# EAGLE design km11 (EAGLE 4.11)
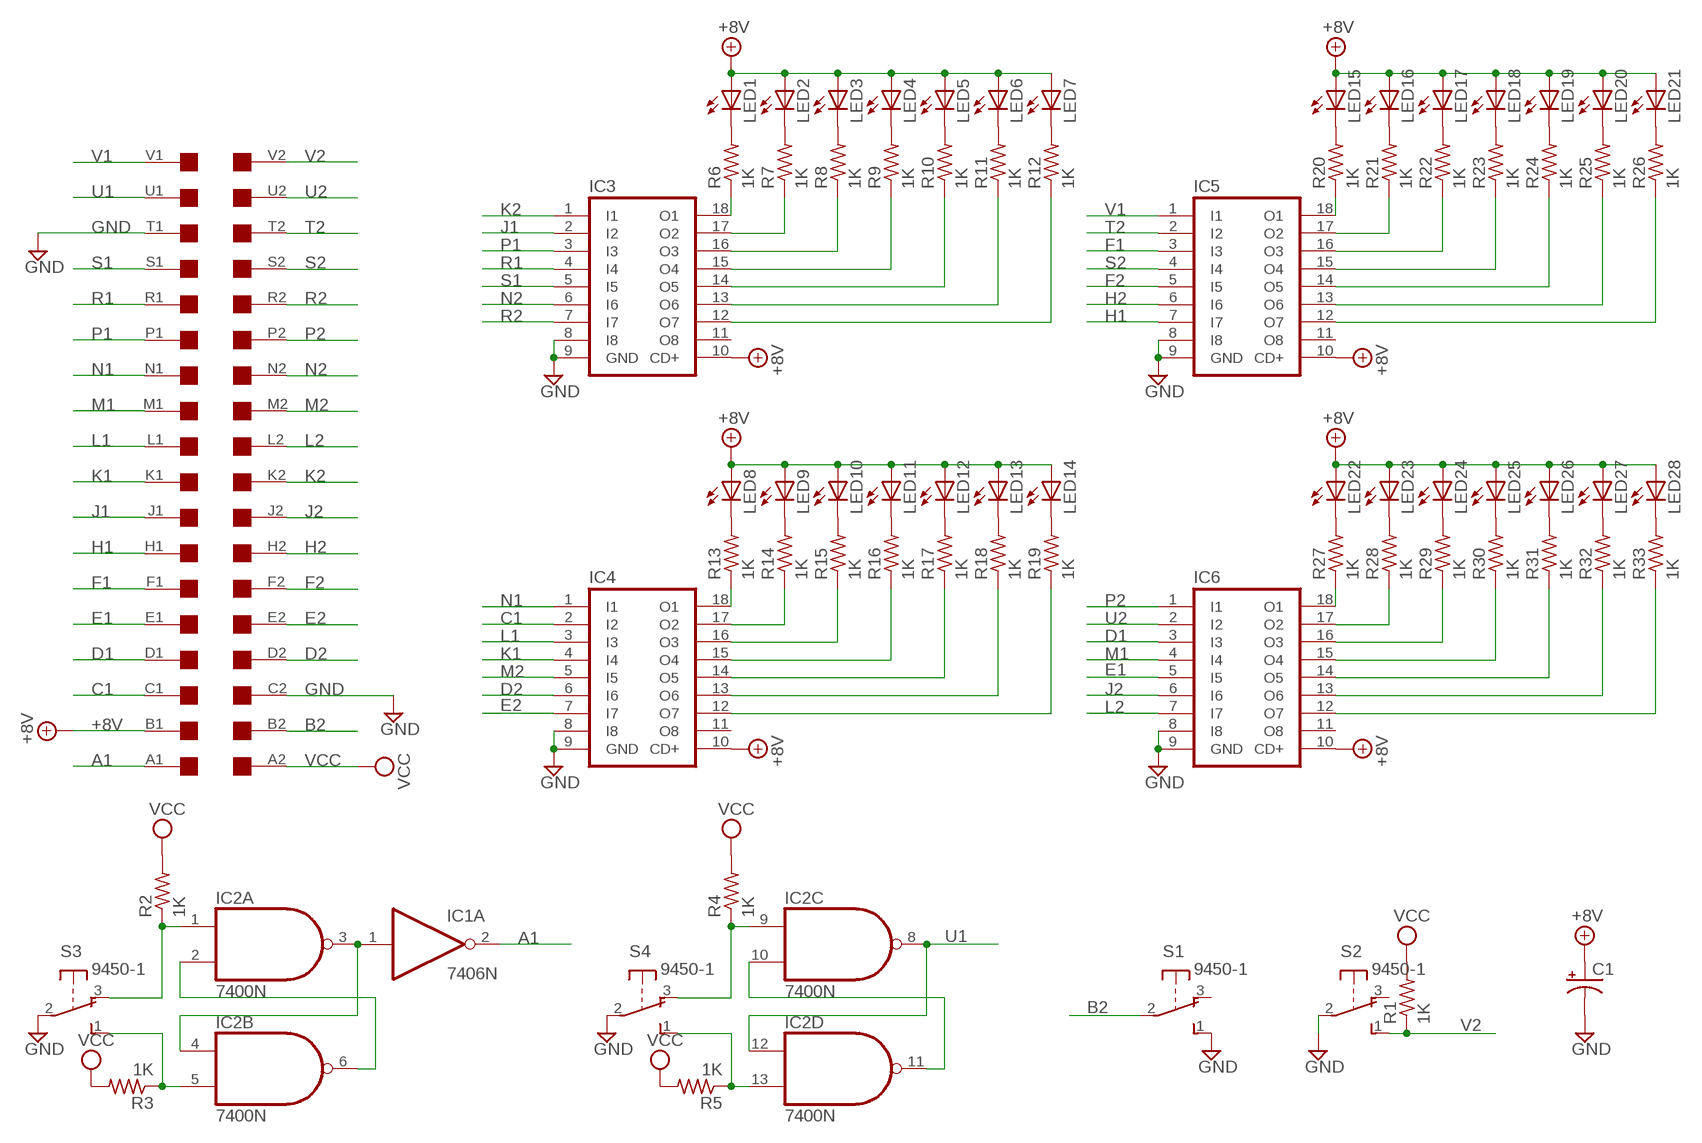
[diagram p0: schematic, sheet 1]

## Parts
C1  CPOL-USE22-6AXIAL  [E22-6]
IC1  7406N  [DIL14]
IC2  7400N  [DIL14]
IC3  ULN2803A  [DIL18]
IC4  ULN2803A  [DIL18]
IC5  ULN2803A  [DIL18]
IC6  ULN2803A  [DIL18]
LED1  LED3MM  [LED3MM]
LED2  LED3MM  [LED3MM]
LED3  LED3MM  [LED3MM]
LED4  LED3MM  [LED3MM]
LED5  LED3MM  [LED3MM]
LED6  LED3MM  [LED3MM]
LED7  LED3MM  [LED3MM]
LED8  LED3MM  [LED3MM]
LED9  LED3MM  [LED3MM]
LED10  LED3MM  [LED3MM]
LED11  LED3MM  [LED3MM]
LED12  LED3MM  [LED3MM]
LED13  LED3MM  [LED3MM]
LED14  LED3MM  [LED3MM]
LED15  LED3MM  [LED3MM]
LED16  LED3MM  [LED3MM]
LED17  LED3MM  [LED3MM]
LED18  LED3MM  [LED3MM]
LED19  LED3MM  [LED3MM]
LED20  LED3MM  [LED3MM]
LED21  LED3MM  [LED3MM]
LED22  LED3MM  [LED3MM]
LED23  LED3MM  [LED3MM]
LED24  LED3MM  [LED3MM]
LED25  LED3MM  [LED3MM]
LED26  LED3MM  [LED3MM]
LED27  LED3MM  [LED3MM]
LED28  LED3MM  [LED3MM]
R1  1K  R-US_0207/10  [0207/10]
R2  1K  R-US_0207/10  [0207/10]
R3  1K  R-US_0207/10  [0207/10]
R4  1K  R-US_0207/10  [0207/10]
R5  1K  R-US_0207/10  [0207/10]
R6  1K  R-US_0207/10  [0207/10]
R7  1K  R-US_0207/10  [0207/10]
R8  1K  R-US_0207/10  [0207/10]
R9  1K  R-US_0207/10  [0207/10]
R10  1K  R-US_0207/10  [0207/10]
R11  1K  R-US_0207/10  [0207/10]
R12  1K  R-US_0207/10  [0207/10]
R13  1K  R-US_0207/10  [0207/10]
R14  1K  R-US_0207/10  [0207/10]
R15  1K  R-US_0207/10  [0207/10]
R16  1K  R-US_0207/10  [0207/10]
R17  1K  R-US_0207/10  [0207/10]
R18  1K  R-US_0207/10  [0207/10]
R19  1K  R-US_0207/10  [0207/10]
R20  1K  R-US_0207/10  [0207/10]
R21  1K  R-US_0207/10  [0207/10]
R22  1K  R-US_0207/10  [0207/10]
R23  1K  R-US_0207/10  [0207/10]
R24  1K  R-US_0207/10  [0207/10]
R25  1K  R-US_0207/10  [0207/10]
R26  1K  R-US_0207/10  [0207/10]
R27  1K  R-US_0207/10  [0207/10]
R28  1K  R-US_0207/10  [0207/10]
R29  1K  R-US_0207/10  [0207/10]
R30  1K  R-US_0207/10  [0207/10]
R31  1K  R-US_0207/10  [0207/10]
R32  1K  R-US_0207/10  [0207/10]
R33  1K  R-US_0207/10  [0207/10]
S1  9450-1  [9450-1]
S2  9450-1  [9450-1]
S3  9450-1  [9450-1]
S4  9450-1  [9450-1]
U$1  EDGE-2  [EDGE-CON2]

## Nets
+8V: C1.+ IC3.10(CD+) IC4.10(CD+) IC5.10(CD+) IC6.10(CD+) LED1.A LED2.A LED3.A LED4.A LED5.A LED6.A LED7.A LED8.A LED9.A LED10.A LED11.A LED12.A LED13.A LED14.A LED15.A LED16.A LED17.A LED18.A LED19.A LED20.A LED21.A LED22.A LED23.A LED24.A LED25.A LED26.A LED27.A LED28.A U$1.B1
A1: IC1.2(A:O) U$1.A1
B2: S1.2(P) U$1.B2
C1: IC4.2(I2) U$1.C1
D1: IC6.3(I3) U$1.D1
D2: IC4.6(I6) U$1.D2
E1: IC6.5(I5) U$1.E1
E2: IC4.7(I7) U$1.E2
F1: IC5.3(I3) U$1.F1
F2: IC5.5(I5) U$1.F2
GND: C1.- IC3.8(I8) IC3.9(GND) IC4.8(I8) IC4.9(GND) IC5.8(I8) IC5.9(GND) IC6.8(I8) IC6.9(GND) S1.1(S) S2.2(P) S3.2(P) S4.2(P) U$1.C2 U$1.T1
H1: IC5.7(I7) U$1.H1
H2: IC5.6(I6) U$1.H2
J1: IC3.2(I2) U$1.J1
J2: IC6.6(I6) U$1.J2
K1: IC4.4(I4) U$1.K1
K2: IC3.1(I1) U$1.K2
L1: IC4.3(I3) U$1.L1
L2: IC6.7(I7) U$1.L2
M1: IC6.4(I4) U$1.M1
M2: IC4.5(I5) U$1.M2
N1: IC4.1(I1) U$1.N1
N2: IC3.6(I6) U$1.N2
N$1: IC1.1(A:I) IC2.3(A:O) IC2.4(B:I0)
N$2: IC2.2(A:I1) IC2.6(B:O)
N$3: IC2.5(B:I1) R3.1 S3.1(S)
N$4: IC2.1(A:I0) R2.1 S3.3(O)
N$5: LED1.K(C) R6.2
N$6: IC2.10(C:I1) IC2.11(D:O)
N$7: IC2.13(D:I1) R5.1 S4.1(S)
N$8: IC2.9(C:I0) R4.1 S4.3(O)
N$9: IC3.18(O1) R6.1
N$10: LED2.K(C) R7.2
N$11: LED3.K(C) R8.2
N$12: LED4.K(C) R9.2
N$13: LED5.K(C) R10.2
N$14: LED6.K(C) R11.2
N$15: LED7.K(C) R12.2
N$16: IC3.17(O2) R7.1
N$17: IC3.16(O3) R8.1
N$18: IC3.15(O4) R9.1
N$19: IC3.14(O5) R10.1
N$20: IC3.13(O6) R11.1
N$21: IC3.12(O7) R12.1
N$29: LED8.K(C) R13.2
N$30: IC4.18(O1) R13.1
N$31: LED9.K(C) R14.2
N$32: LED10.K(C) R15.2
N$33: LED11.K(C) R16.2
N$34: LED12.K(C) R17.2
N$35: LED13.K(C) R18.2
N$36: LED14.K(C) R19.2
N$37: IC4.17(O2) R14.1
N$38: IC4.16(O3) R15.1
N$39: IC4.15(O4) R16.1
N$40: IC4.14(O5) R17.1
N$41: IC4.13(O6) R18.1
N$42: IC4.12(O7) R19.1
N$43: LED15.K(C) R20.2
N$44: IC5.18(O1) R20.1
N$45: LED16.K(C) R21.2
N$46: LED17.K(C) R22.2
N$47: LED18.K(C) R23.2
N$48: LED19.K(C) R24.2
N$49: LED20.K(C) R25.2
N$50: LED21.K(C) R26.2
N$51: IC5.17(O2) R21.1
N$52: IC5.16(O3) R22.1
N$53: IC5.15(O4) R23.1
N$54: IC5.14(O5) R24.1
N$55: IC5.13(O6) R25.1
N$56: IC5.12(O7) R26.1
N$57: LED22.K(C) R27.2
N$58: IC6.18(O1) R27.1
N$59: LED23.K(C) R28.2
N$60: LED24.K(C) R29.2
N$61: LED25.K(C) R30.2
N$62: LED26.K(C) R31.2
N$63: LED27.K(C) R32.2
N$64: LED28.K(C) R33.2
N$65: IC6.17(O2) R28.1
N$66: IC6.16(O3) R29.1
N$67: IC6.15(O4) R30.1
N$68: IC6.14(O5) R31.1
N$69: IC6.13(O6) R32.1
N$70: IC6.12(O7) R33.1
P1: IC3.3(I3) U$1.P1
P2: IC6.1(I1) U$1.P2
R1: IC3.4(I4) U$1.R1
R2: IC3.7(I7) U$1.R2
S1: IC3.5(I5) U$1.S1
S2: IC5.4(I4) U$1.S2
T2: IC5.2(I2) U$1.T2
U1: IC2.8(C:O) IC2.12(D:I0) U$1.U1
U2: IC6.2(I2) U$1.U2
V1: IC5.1(I1) U$1.V1
V2: R1.1 S2.1(S) U$1.V2
VCC: R1.2 R2.2 R3.2 R4.2 R5.2 U$1.A2
Unconnected: IC1.3(B:I) IC1.4(B:O) IC1.5(C:I) IC1.6(C:O) IC1.8(D:O) IC1.9(D:I) IC1.10(E:O) IC1.11(E:I) IC1.12(F:O) IC1.13(F:I) IC3.11(O8) IC4.11(O8) IC5.11(O8) IC6.11(O8) S1.3(O) S2.3(O)

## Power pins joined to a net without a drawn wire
GND: IC1.7(P:GND) IC2.7(P:GND)
VCC: IC1.14(P:VCC) IC2.14(P:VCC)

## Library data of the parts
C1 = rcl:CPOL-US: POLARIZED CAPACITOR, American symbol
IC1 = 74xx-us:74*06: Hex INVERTER, open collector high-voltage output
IC2 = 74xx-us:74*00: Quad 2-input NAND gate
IC3-IC6 = uln-udn:ULN2803A: DRIVER ARRAY
LED1-LED28 = led:LED: LED
R1-R33 = rcl:R-US_: RESISTOR, American symbol
S1-S4 = switch-misc:9450-1: MARQUARDT SWITCH
U$1 = dec-con:EDGE-2: Double-Sided DEC edge connector.

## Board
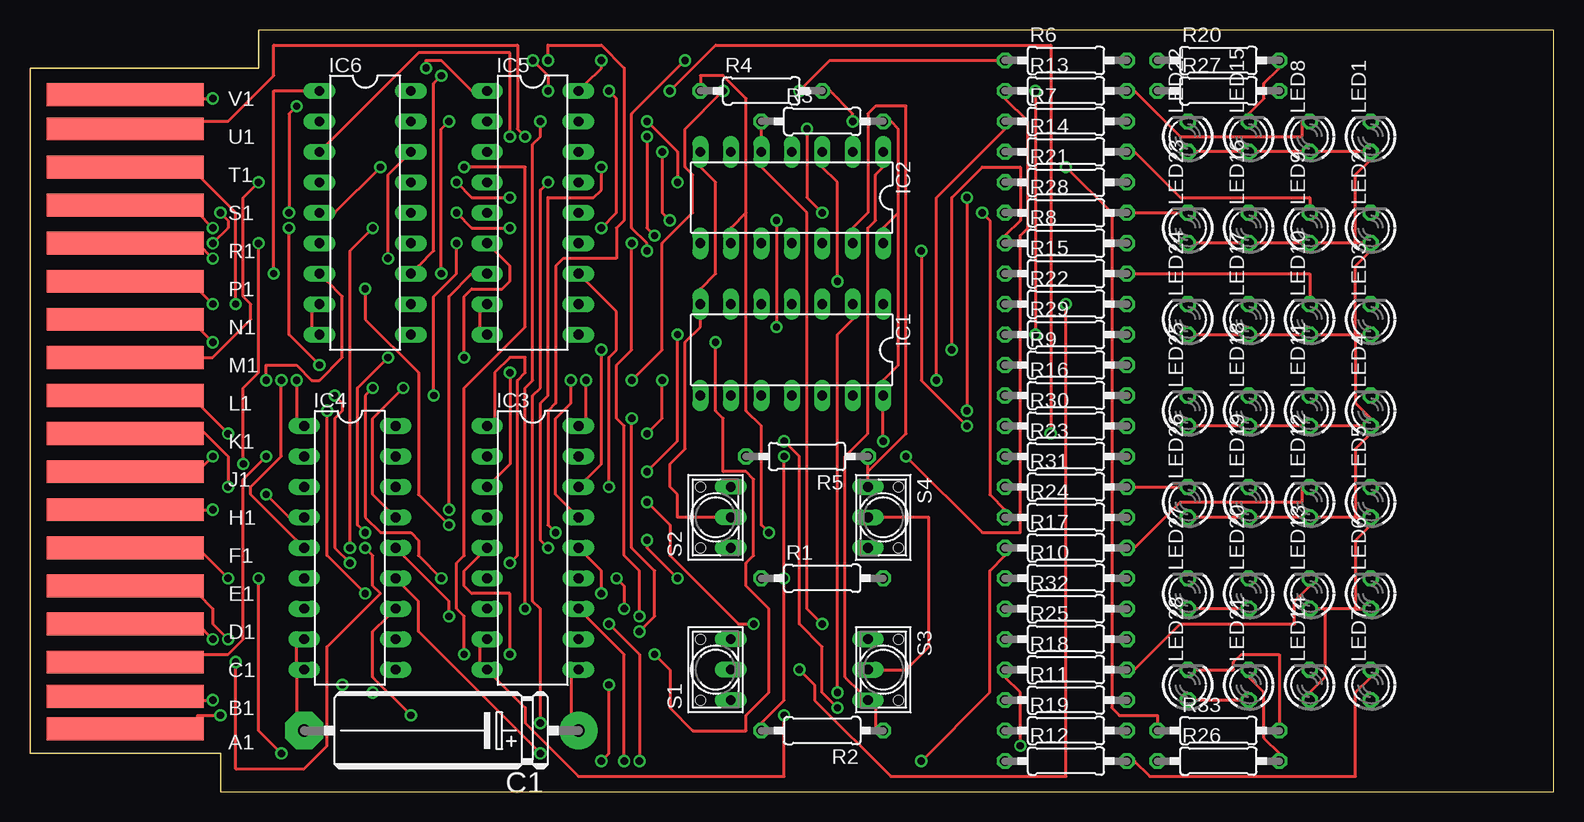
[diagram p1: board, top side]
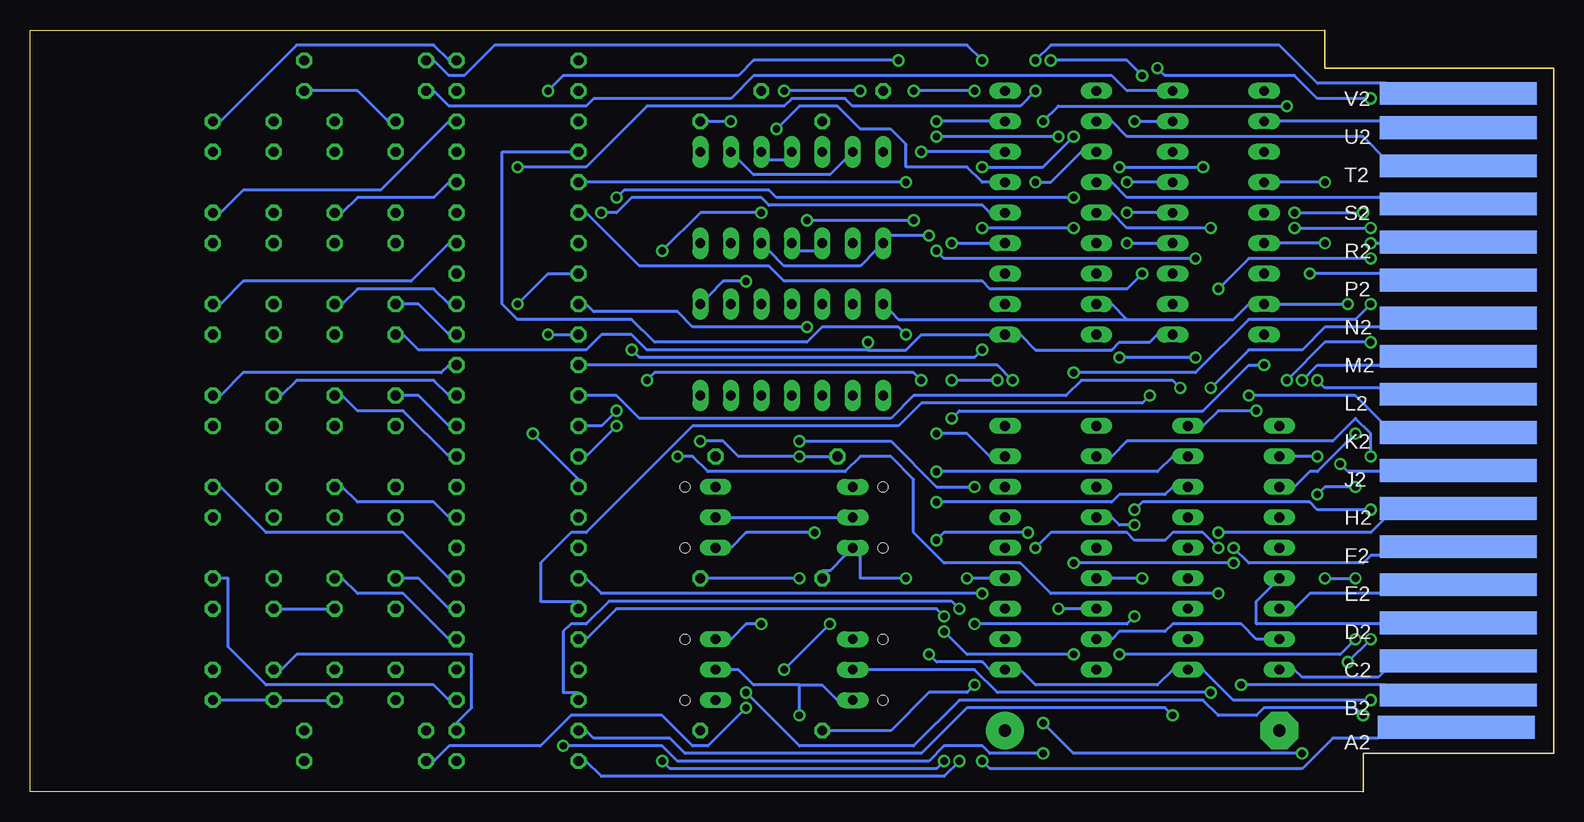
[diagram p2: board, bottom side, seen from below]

Size 127 x 63.5 mm. Coordinates in mm from the lower left corner, seen from the top.
Outline: 15.88,0 127,0 127,63.5 19.05,63.5
Copper layers (1*16): Top 0.035mm / dielectric 1.5mm / Bottom 0.035mm
Design rules "default": minimum track width 10mil, minimum drill 24mil, track to track 8mil, track to pad 8mil, pad to pad 8mil, via to via 8mil, smd to smd 8mil, copper to edge 40mil, drill to drill 8mil, minimum pad ring 10mil, minimum via ring 8mil, stop-mask expansion 4mil, vias tented up to drill 0mil, thermal gap 10mil

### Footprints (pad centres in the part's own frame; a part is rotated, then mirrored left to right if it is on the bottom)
E22-6 = drill 1.016 pad 3.15 round: + -11.43,0 | drill 1.016 pad 3.15 octagon: - 11.43,0
DIL14 = drill 0.813 long: 1 -7.62,-3.81; 2 -5.08,-3.81; 3 -2.54,-3.81; 4 0,-3.81; 5 2.54,-3.81; 6 5.08,-3.81; 7 7.62,-3.81; 8 7.62,3.81; 9 5.08,3.81; 10 2.54,3.81; 11 0,3.81; 12 -2.54,3.81; 13 -5.08,3.81; 14 -7.62,3.81
DIL18 = drill 0.813 long: 1 -10.16,-3.81; 2 -7.62,-3.81; 3 -5.08,-3.81; 4 -2.54,-3.81; 5 0,-3.81; 6 2.54,-3.81; 7 5.08,-3.81; 8 7.62,-3.81; 9 10.16,-3.81; 10 10.16,3.81; 11 7.62,3.81; 12 5.08,3.81; 13 2.54,3.81; 14 0,3.81; 15 -2.54,3.81; 16 -5.08,3.81; 17 -7.62,3.81; 18 -10.16,3.81
LED3MM = drill 0.813 octagon: A -1.27,0; K 1.27,0
0207/10 = drill 0.813 octagon: 1 -5.08,0; 2 5.08,0
9450-1 = drill 0.813 long: 1 -2.54,-1.27; 2 0,-1.27; 3 2.54,-1.27 | hole 0.813: 2.54,1.27; -2.54,1.27
EDGE-CON2 = smd 13.106 x 1.905: A1 7.938,5.239; B1 7.938,7.938; C1 7.938,10.795; D1 7.938,13.97; E1 7.938,17.145; F1 7.938,20.32; H1 7.938,23.495; J1 7.938,26.67; K1 7.938,29.845; L1 7.938,33.02; M1 7.938,36.195; N1 7.938,39.37; P1 7.938,42.545; R1 7.938,45.72; S1 7.938,48.895; T1 7.938,52.07; U1 7.938,55.245; V1 7.938,58.102 | smd 13.106 x 1.905 bottom: A2 8.096,5.34; B2 7.938,8.039; C2 7.938,10.897; D2 7.938,14.072; E2 7.938,17.247; F2 7.938,20.422; H2 7.938,23.597; J2 7.938,26.772; K2 7.938,29.947; L2 7.938,33.122; M2 7.938,36.297; N2 7.938,39.472; P2 7.938,42.647; R2 7.938,45.822; S2 7.938,48.997; T2 7.938,52.172; U2 7.938,55.347; V2 7.938,58.204

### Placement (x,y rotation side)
C1  34.29,5.08 180 top
IC1  63.5,36.83 180 top
IC2  63.5,49.53 180 top
IC3  41.91,20.32 270 top
IC4  26.67,20.32 270 top
IC5  41.91,48.26 270 top
IC6  27.94,48.26 270 top
LED1  111.76,54.61 90 top
LED2  111.76,46.99 90 top
LED3  111.76,39.37 90 top
LED4  111.76,31.75 90 top
LED5  111.76,24.13 90 top
LED6  111.76,16.51 90 top
LED7  111.76,8.89 90 top
LED8  106.68,54.61 90 top
LED9  106.68,46.99 90 top
LED10  106.68,39.37 90 top
LED11  106.68,31.75 90 top
LED12  106.68,24.13 90 top
LED13  106.68,16.51 90 top
LED14  106.68,8.89 90 top
LED15  101.6,54.61 90 top
LED16  101.6,46.99 90 top
LED17  101.6,39.37 90 top
LED18  101.6,31.75 90 top
LED19  101.6,24.13 90 top
LED20  101.6,16.51 90 top
LED21  101.6,8.89 90 top
LED22  96.52,54.61 90 top
LED23  96.52,46.99 90 top
LED24  96.52,39.37 90 top
LED25  96.52,31.75 90 top
LED26  96.52,24.13 90 top
LED27  96.52,16.51 90 top
LED28  96.52,8.89 90 top
R1  66.04,17.78 0 top
R2  66.04,5.08 180 top
R3  66.04,55.88 0 top
R4  60.96,58.42 0 top
R5  64.77,27.94 180 top
R6  86.36,60.96 0 top
R7  86.36,55.88 0 top
R8  86.36,45.72 0 top
R9  86.36,35.56 0 top
R10  86.36,17.78 0 top
R11  86.36,7.62 0 top
R12  86.36,2.54 0 top
R13  86.36,58.42 0 top
R14  86.36,53.34 0 top
R15  86.36,43.18 0 top
R16  86.36,33.02 0 top
R17  86.36,20.32 0 top
R18  86.36,10.16 0 top
R19  86.36,5.08 0 top
R20  99.06,60.96 0 top
R21  86.36,50.8 0 top
R22  86.36,40.64 0 top
R23  86.36,27.94 0 top
R24  86.36,22.86 0 top
R25  86.36,12.7 0 top
R26  99.06,2.54 0 top
R27  99.06,58.42 0 top
R28  86.36,48.26 0 top
R29  86.36,38.1 0 top
R30  86.36,30.48 0 top
R31  86.36,25.4 0 top
R32  86.36,15.24 0 top
R33  99.06,5.08 0 top
S1  57.15,10.16 90 top
S2  57.15,22.86 90 top
S3  71.12,10.16 270 top
S4  71.12,22.86 270 top
U$1  0,0 0 top

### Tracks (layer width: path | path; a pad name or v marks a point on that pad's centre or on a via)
+8V  (via drill 0.61)
  Top 0.254: C1.+ 45.09,6.35 45.09,9.53 IC3.10 | v15.24,7.62 13.97,7.62 U$1.B1 | LED25.A 97.16,30.48 100.97,30.48 LED18.A 102.23,30.48 106.05,30.48 LED11.A 107.31,30.48 111.12,30.48 LED4.A | LED26.A 97.16,22.86 100.97,22.86 LED19.A 102.23,22.86 106.05,22.86 LED12.A 107.31,22.86 110.49,22.86 | 110.49,22.86 111.12,22.86 LED5.A 111.76,22.23 110.49,20.95 110.49,15.24 | LED28.A 97.16,7.62 100.97,7.62 LED21.A | LED27.A 97.16,15.24 100.97,15.24 LED20.A | 107.95,15.24 107.31,15.24 LED13.A | 110.49,15.24 107.95,15.24 | 110.49,15.24 111.12,15.24 LED6.A | 107.95,15.24 107.95,9.53 106.68,8.26 LED14.A | 110.49,22.86 110.49,28.57 111.76,29.84 LED4.A | LED22.A 97.16,53.34 100.97,53.34 LED15.A 102.23,53.34 106.05,53.34 LED8.A 107.31,53.34 111.12,53.34 LED1.A 111.76,52.7 110.49,51.44 110.49,45.72 | LED23.A 97.16,45.72 100.97,45.72 LED16.A 102.23,45.72 106.05,45.72 LED9.A 107.31,45.72 110.49,45.72 | 110.49,45.72 111.12,45.72 LED2.A 111.76,45.09 110.49,43.81 110.49,38.1 | LED24.A 97.16,38.1 100.97,38.1 LED17.A 102.23,38.1 106.05,38.1 LED10.A 107.31,38.1 110.49,38.1 | 110.49,38.1 111.12,38.1 LED3.A | 110.49,38.1 110.49,32.38 111.76,31.11 LED4.A | v52.07,11.43 53.34,10.16 53.34,6.99 55.24,5.08 59.69,5.08 59.69,6.35 61.59,8.26 61.59,15.24 59.69,17.14 59.69,19.05 60.33,19.68 60.33,26.04 59.69,26.67 57.78,26.67 57.78,31.11 57.15,31.75 v57.15,37.47
  Bottom 0.254: v15.24,7.62 26.67,7.62 29.21,10.16 IC4.10 31.75,10.16 33.02,8.89 43.18,8.89 44.45,10.16 IC3.10 46.99,10.16 47.62,10.79 51.44,10.79 v52.07,11.43 | LED21.A 102.23,7.62 106.05,7.62 LED14.A 107.31,7.62 111.12,7.62 LED7.A | LED13.A 106.05,15.24 102.23,15.24 LED20.A | IC6.10 33.02,38.1 33.66,37.47 36.2,37.47 36.83,36.83 43.18,36.83 44.45,38.1 IC5.10 46.99,38.1 52.7,38.1 53.98,36.83 57.15,36.83 | 57.15,36.83 75.56,36.83 76.83,38.1 79.38,38.1 80.64,36.83 94.61,36.83 95.89,38.1 LED24.A | v57.15,37.47 57.15,36.83
A1  (via drill 0.61)
  Top 0.254: v67.31,8.26 67.31,38.1 68.58,39.37 IC1.2 | v15.88,6.35 13.97,6.35 13.97,5.71 U$1.A1
  Bottom 0.254: v67.31,8.26 62.87,3.81 53.34,3.81 49.53,7.62 29.21,7.62 27.94,6.35 24.77,6.35 24.13,6.99 16.51,6.99 v15.88,6.35
B2  (via drill 0.61)
  Top 0.254: v28.57,8.26 26.04,8.26 v26.04,8.89
  Bottom 0.254: v28.57,8.26 46.35,8.26 48.26,10.16 57.15,10.16 S1.2 | v26.04,8.89 13.97,8.89 U$1.B2
C1  (via drill 0.61)
  Top 0.254: v19.68,27.94 17.78,26.04 17.78,12.7 16.51,11.43 13.97,11.43 U$1.C1
  Bottom 0.254: v19.68,27.94 21.59,27.94 IC4.2
D1  (via drill 0.61)
  Top 0.254: v40.01,54.61 40.01,61.59 32.38,61.59 24.77,53.98 IC6.3 | v47.62,52.07 47.62,50.16 46.99,49.53 43.18,49.53 43.18,33.02 42.55,32.38 42.55,20.95 v43.18,20.32 | v27.94,20.32 28.57,19.68 28.57,17.14 29.21,16.51 24.77,12.06 24.77,3.81 22.86,1.91 17.14,1.91 v17.14,10.79 | v15.24,12.7 13.97,13.97 U$1.D1
  Bottom 0.254: v40.01,54.61 42.55,52.07 v47.62,52.07 | v43.18,20.32 41.91,21.59 35.56,21.59 34.92,20.95 32.38,20.95 31.75,21.59 29.21,21.59 v27.94,20.32 | v17.14,10.79 v15.24,12.7
D2
  Bottom 0.254: IC4.6 23.5,17.14 24.77,15.88 24.77,13.97 13.97,13.97 U$1.D2
E1  (via drill 0.61)
  Top 0.254: v29.21,52.07 25.4,48.26 IC6.5 | v36.2,52.07 41.27,52.07 41.27,38.73 36.2,33.66 36.2,19.68 35.56,19.05 35.56,15.24 36.2,14.61 v36.2,11.43 | v16.51,12.7 15.24,13.97 15.24,15.24 13.97,16.51 U$1.E1
  Bottom 0.254: v36.2,52.07 v29.21,52.07 | v36.2,11.43 17.78,11.43 v16.51,12.7
E2
  Bottom 0.254: IC4.7 21.59,15.24 20.32,16.51 13.97,16.51 U$1.E2
F1  (via drill 0.61)
  Top 0.254: v43.18,50.8 42.55,50.16 42.55,33.66 41.91,33.02 41.91,15.88 42.55,15.24 v42.55,5.71 | v20.95,3.17 19.05,5.08 v19.05,17.78 | v16.51,17.78 13.97,20.32 U$1.F1
  Bottom 0.254: v43.18,50.8 41.91,50.8 39.37,53.34 IC5.3 | v42.55,5.71 40.01,3.17 v20.95,3.17 | v19.05,17.78 v16.51,17.78
F2  (via drill 0.61)
  Top 0.254: v28.57,46.99 26.67,45.09 v26.67,20.32
  Bottom 0.254: v28.57,46.99 35.56,46.99 36.83,48.26 IC5.5 | v26.67,20.32 25.4,19.05 15.88,19.05 15.24,19.68 13.97,19.68 U$1.F2
GND  (via drill 0.61)
  Top 0.254: IC3.8 37.47,12.06 37.47,10.79 IC3.9 38.73,9.53 41.27,6.99 41.27,5.71 45.72,1.27 62.87,1.27 v62.87,6.35 | IC4.8 22.23,12.06 22.23,10.79 IC4.9 22.23,9.53 22.23,6.35 C1.- | S4.2 71.12,22.86 74.93,22.86 74.93,12.06 73.03,10.16 71.12,10.16 S3.2 | IC2.7 55.88,52.07 57.15,50.8 57.15,43.18 55.88,41.91 IC1.7 55.88,39.37 55.88,38.73 54.61,37.47 54.61,28.57 53.34,27.3 53.34,25.4 53.98,24.77 53.98,22.86 57.15,22.86 S2.2 | IC6.9 23.5,38.73 23.5,40.01 IC6.8 | IC5.9 37.47,38.73 37.47,40.01 IC5.8 | v17.14,40.64 17.14,48.26 13.97,51.44 U$1.T1
  Bottom 0.254: IC3.8 36.83,12.7 36.2,13.34 32.38,13.34 31.75,13.97 26.04,13.97 24.77,12.7 24.13,12.7 IC4.8 | IC4.9 21.59,10.16 20.95,9.53 14.61,9.53 13.97,10.16 U$1.C2 | S2.2 59.69,22.86 68.58,22.86 S4.2 | 62.87,8.89 66.67,8.89 67.94,10.16 68.58,10.16 S3.2 | 62.87,8.89 60.96,8.89 59.69,7.62 S1.1 | 35.56,39.37 26.67,39.37 25.4,40.64 IC6.8 22.86,40.64 v17.14,40.64 | 35.56,39.37 36.83,40.64 IC5.8 | 35.56,39.37 54.61,39.37 55.24,40.01 IC1.7 | v62.87,6.35 62.87,8.89
H1  (via drill 0.61)
  Top 0.254: v34.92,23.5 34.92,41.27 36.83,43.18 IC5.7 | v15.24,23.5 13.97,23.5 U$1.H1
  Bottom 0.254: v34.92,23.5 34.29,24.13 20.32,24.13 19.68,23.5 v15.24,23.5
H2  (via drill 0.61)
  Top 0.254: v36.2,36.2 36.2,41.27 36.83,41.91 39.37,41.91 40.01,42.55 40.01,43.81 38.73,45.09 IC5.6 | v29.84,36.2 27.3,33.66 27.3,22.23 v27.94,21.59
  Bottom 0.254: v29.84,36.2 v36.2,36.2 | v27.94,21.59 15.24,21.59 13.97,22.86 U$1.H2
J1  (via drill 0.61)
  Top 0.254: v15.24,27.94 13.97,26.67 U$1.J1
  Bottom 0.254: v15.24,27.94 15.24,29.84 16.51,31.11 18.41,29.21 35.56,29.21 36.83,27.94 IC3.2
J2  (via drill 0.61)
  Top 0.254: v19.05,45.72 19.05,34.92 17.78,33.66 v17.78,27.3
  Bottom 0.254: v19.05,45.72 22.86,45.72 IC6.6 | v17.78,27.3 17.14,26.67 13.97,26.67 U$1.J2
K1  (via drill 0.61)
  Top 0.254: v19.68,24.77 21.59,22.86 IC4.4 | v16.51,25.4 16.51,27.94 13.97,30.48 U$1.K1
  Bottom 0.254: v19.68,24.77 19.05,25.4 v16.51,25.4
K2  (via drill 0.61)
  Top 0.254: v40.01,19.05 40.64,19.68 40.64,34.29 41.27,34.92 41.27,36.2 40.01,36.2 38.73,34.92 38.73,31.11 IC3.1 | v26.67,19.05 25.4,20.32 25.4,31.11 26.04,31.75 26.04,32.38 v25.4,33.02
  Bottom 0.254: v26.67,19.05 v40.01,19.05 | v25.4,33.02 16.51,33.02 13.97,30.48 U$1.K2
L1  (via drill 0.61)
  Top 0.254: v16.51,29.84 13.97,32.38 U$1.L1
  Bottom 0.254: v16.51,29.84 19.68,26.67 20.32,26.67 21.59,25.4 IC4.3
L2  (via drill 0.61)
  Top 0.254: v19.68,34.29 19.68,35.56 22.23,35.56 23.5,34.29 24.13,34.29 26.04,36.2 26.04,41.27 24.77,42.55 IC6.7
  Bottom 0.254: v19.68,34.29 19.05,33.66 13.97,33.66 U$1.L2
M1  (via drill 0.61)
  Top 0.254: v19.05,50.8 17.78,49.53 17.78,41.27 18.41,40.64 18.41,39.37 15.24,36.2 13.97,36.2 U$1.M1
  Bottom 0.254: v19.05,50.8 22.86,50.8 IC6.4
M2  (via drill 0.61)
  Top 0.254: v20.95,34.29 20.95,27.94 18.41,25.4 18.41,24.77 22.23,20.95 IC4.5
  Bottom 0.254: v20.95,34.29 19.68,35.56 13.97,35.56 U$1.M2
N1  (via drill 0.61)
  Top 0.254: v22.23,34.29 22.23,31.11 IC4.1 | v15.24,37.47 13.97,38.73 U$1.N1
  Bottom 0.254: v22.23,34.29 19.05,37.47 v15.24,37.47
N2  (via drill 0.61)
  Top 0.254: v34.29,17.78 32.38,19.68 32.38,20.95 31.75,21.59 29.21,21.59 27.94,22.86 27.94,33.02 v28.57,33.66
  Bottom 0.254: v34.29,17.78 36.83,17.78 IC3.6 | v28.57,33.66 25.4,36.83 20.95,36.83 19.05,38.73 13.97,38.73 U$1.N2
N$1  (via drill 0.61)
  Top 0.254: v67.31,42.55 67.31,50.8 66.04,52.07 IC2.3
  Bottom 0.254: IC2.4 64.14,52.7 65.41,52.7 IC2.3 | v67.31,42.55 69.22,42.55 70.48,41.27 IC1.1
N$2
  Bottom 0.254: IC2.6 59.05,52.7 60.33,51.44 66.67,51.44 67.94,52.7 IC2.2
N$3  (via drill 0.61)
  Top 0.254: R3.1 60.96,55.24 60.96,54.61 IC2.5 60.96,52.07 64.77,48.26 64.77,15.24 v66.04,13.97
  Bottom 0.254: v66.04,13.97 67.31,13.97 68.58,12.7 S3.1
N$4
  Top 0.254: R2.1 70.48,5.08 70.48,6.99 S3.3 69.22,8.26 67.94,9.53 67.94,27.94 69.85,29.84 69.85,46.99 70.48,47.62 70.48,51.44 71.12,52.07 IC2.1
N$5
  Bottom 0.254: R6.2 92.08,60.96 93.34,62.23 104.78,62.23 111.12,55.88 LED1.K
N$6
  Bottom 0.254: IC2.10 61.59,45.09 62.87,45.09 IC2.11
N$7
  Top 0.254: 69.85,26.67 69.85,27.3 R5.1 | 69.85,26.67 69.85,26.04 S4.1 | 69.85,26.67 73.03,29.84 73.03,57.15 70.48,57.15 69.85,56.52 69.85,48.26 68.58,46.99 IC2.13
N$8  (via drill 0.61)
  Top 0.254: 59.69,48.26 58.42,46.99 IC2.9 | 59.69,48.26 59.69,57.78 57.78,59.69 55.88,59.69 55.88,59.05 R4.1 | v61.59,21.59 60.96,22.23 60.96,30.48 59.69,31.75 59.69,48.26
  Bottom 0.254: v61.59,21.59 67.31,21.59 68.58,20.32 S4.3
N$9  (via drill 0.61)
  Top 0.254: v46.35,34.29 46.35,31.11 IC3.18 | v50.16,34.29 52.7,36.83 52.7,45.72 55.24,48.26 55.24,51.44 54.61,52.07 54.61,55.24 v57.78,58.42 | v64.14,58.42 66.67,60.96 80.64,60.96 R6.1
  Bottom 0.254: v46.35,34.29 v50.16,34.29 | v57.78,58.42 v64.14,58.42
N$10
  Bottom 0.254: R7.2 92.08,55.88 97.79,50.16 109.22,50.16 111.12,48.26 LED2.K
N$11
  Bottom 0.254: R8.2 92.08,45.72 95.25,42.55 109.22,42.55 111.12,40.64 LED3.K
N$12
  Bottom 0.254: R9.2 92.08,35.56 92.71,34.92 109.22,34.92 111.12,33.02 LED4.K
N$13
  Bottom 0.254: R10.2 92.08,17.78 95.89,21.59 107.31,21.59 111.12,25.4 LED5.K
N$14
  Bottom 0.254: R11.2 92.08,7.62 93.34,8.89 107.31,8.89 110.49,12.06 110.49,17.78 111.12,17.78 LED6.K
N$15
  Top 0.254: R12.2 92.08,2.54 93.34,1.27 110.49,1.27 110.49,8.26 111.76,9.53 LED7.K
N$16  (via drill 0.61)
  Top 0.254: v51.44,29.84 52.7,31.11 v52.7,34.29 | v75.56,34.29 75.56,49.53 81.28,55.24 R7.1
  Bottom 0.254: v51.44,29.84 48.9,29.84 46.99,27.94 IC3.17 | v52.7,34.29 53.34,34.92 74.93,34.92 v75.56,34.29
N$17  (via drill 0.61)
  Top 0.254: v47.62,36.83 47.62,27.3 46.35,26.04 IC3.16 | v76.83,36.83 76.83,49.53 79.38,52.07 82.55,52.07 82.55,47.62 81.28,46.35 R8.1
  Bottom 0.254: v47.62,36.83 48.26,36.2 76.2,36.2 v76.83,36.83
N$18  (via drill 0.61)
  Top 0.254: v45.09,34.29 45.09,32.38 43.81,31.11 43.81,24.77 45.09,23.5 IC3.15
  Bottom 0.254: v45.09,34.29 46.35,35.56 80.64,35.56 R9.1
N$19  (via drill 0.61)
  Top 0.254: v47.62,16.51 47.62,18.41 46.35,19.68 IC3.14
  Bottom 0.254: v47.62,16.51 79.38,16.51 80.64,17.78 R10.1
N$20  (via drill 0.61)
  Top 0.254: v48.9,17.78 49.53,17.14 v49.53,15.24
  Bottom 0.254: v48.9,17.78 46.99,17.78 IC3.13 | v49.53,15.24 50.16,15.88 78.74,15.88 80.64,13.97 81.92,13.97 82.55,13.34 82.55,8.26 81.28,8.26 R11.1
N$21  (via drill 0.61)
  Top 0.254: v49.53,2.54 49.53,11.43 46.35,14.61 IC3.12
  Bottom 0.254: v49.53,2.54 50.8,1.27 79.38,1.27 80.64,2.54 R12.1
N$29
  Top 0.254: R13.2 92.08,58.42 95.89,54.61 106.05,54.61 106.05,55.88 LED8.K
N$30  (via drill 0.61)
  Top 0.254: v24.77,31.75 24.77,19.68 v27.94,16.51 | v73.03,27.94 79.38,21.59 82.55,21.59 82.55,46.35 83.19,46.99 83.19,55.88 81.28,57.78 R13.1
  Bottom 0.254: v24.77,31.75 27.94,31.75 29.21,30.48 IC4.18 | v27.94,16.51 41.91,16.51 44.45,19.05 50.8,19.05 53.34,21.59 53.34,26.04 55.24,27.94 57.78,27.94 59.05,26.67 70.48,26.67 71.75,27.94 v73.03,27.94
N$31
  Top 0.254: R14.2 92.08,53.34 95.89,49.53 106.68,49.53 106.68,48.9 LED9.K
N$32
  Top 0.254: R15.2 92.08,43.18 106.68,43.18 106.68,41.27 LED10.K
N$33
  Bottom 0.254: R16.2 92.08,33.02 93.34,34.29 104.78,34.29 106.05,33.02 LED11.K
N$34
  Top 0.254: R17.2 92.08,20.32 95.89,24.13 106.05,24.13 106.05,25.4 LED12.K
N$35
  Top 0.254: R18.2 92.08,10.16 95.89,13.97 105.41,13.97 105.41,15.88 106.68,17.14 LED13.K
N$36
  Bottom 0.254: R19.2 91.44,5.71 90.17,6.99 90.17,11.43 104.78,11.43 106.05,10.16 LED14.K
N$37  (via drill 0.61)
  Top 0.254: v51.44,26.67 53.98,29.21 v53.98,38.1
  Bottom 0.254: v51.44,26.67 33.02,26.67 31.75,27.94 IC4.17 | v53.98,38.1 54.61,38.73 60.96,38.73 62.23,37.47 74.93,37.47 76.83,39.37 86.36,39.37 87.63,40.64 87.63,53.34 81.92,53.34 R14.1
N$38  (via drill 0.61)
  Top 0.254: v51.44,24.13 53.34,22.23 53.34,19.68 59.05,13.97 v60.33,13.97 | v64.14,10.16 65.41,8.89 65.41,7.62 71.75,1.27 86.36,1.27 v86.36,40.64
  Bottom 0.254: v51.44,24.13 36.83,24.13 36.2,24.77 32.38,24.77 31.75,25.4 IC4.16 | v60.33,13.97 v64.14,10.16 | v86.36,40.64 83.82,43.18 81.92,43.18 R15.1
N$39  (via drill 0.61)
  Top 0.254: v31.11,33.66 28.57,31.11 28.57,24.77 29.84,23.5 IC4.15
  Bottom 0.254: v31.11,33.66 31.75,34.29 39.37,34.29 40.64,33.02 53.34,33.02 55.24,31.11 76.2,31.11 78.11,33.02 80.64,33.02 R16.1
N$40  (via drill 0.61)
  Top 0.254: v34.92,14.61 34.92,15.88 31.11,19.68 IC4.14 | v48.26,13.97 50.8,11.43 v50.8,2.54 | v74.3,2.54 80.01,8.26 80.01,18.41 81.28,19.68 R17.1
  Bottom 0.254: v34.92,14.61 35.56,13.97 v48.26,13.97 | v50.8,2.54 51.44,1.91 73.66,1.91 v74.3,2.54
N$41  (via drill 0.61)
  Top 0.254: v82.55,3.81 82.55,8.26 81.28,9.53 R18.1 | v42.55,3.17 32.38,13.34 32.38,15.88 31.11,17.14 IC4.13
  Bottom 0.254: v82.55,3.81 74.3,3.81 73.03,2.54 52.07,2.54 50.8,3.81 47.62,3.81 46.99,3.17 v42.55,3.17
N$42  (via drill 0.61)
  Top 0.254: v31.75,6.35 28.57,9.53 28.57,13.34 29.84,14.61 IC4.12
  Bottom 0.254: v31.75,6.35 32.38,6.99 48.9,6.99 52.7,3.17 72.39,3.17 73.66,4.45 80.01,4.45 80.64,5.08 R19.1
N$43
  Top 0.254: LED15.K 101.6,56.52 102.87,57.78 102.87,59.05 104.14,60.33 R20.2
N$44  (via drill 0.61)
  Top 0.254: v47.62,60.96 47.62,60.33 46.35,59.05 IC5.18
  Bottom 0.254: v47.62,60.96 48.9,62.23 88.27,62.23 90.81,59.69 92.08,59.69 93.34,60.96 R20.1
N$45
  Bottom 0.254: R21.2 92.08,50.8 93.34,49.53 99.69,49.53 100.97,48.26 LED16.K
N$46
  Bottom 0.254: R22.2 92.08,40.64 93.34,41.91 99.69,41.91 100.97,40.64 LED17.K
N$47
  Bottom 0.254: R23.2 92.08,27.94 95.89,31.75 99.69,31.75 100.97,33.02 LED18.K
N$48
  Bottom 0.254: R24.2 92.08,22.86 93.34,24.13 99.69,24.13 100.97,25.4 LED19.K
N$49
  Bottom 0.254: R25.2 92.08,12.7 95.89,16.51 99.69,16.51 100.97,17.78 LED20.K
N$50
  Top 0.254: R26.2 104.14,3.17 102.87,4.45 102.87,8.26 101.6,9.53 LED21.K
N$51  (via drill 0.61)
  Top 0.254: v51.44,55.88 53.98,53.34 v53.98,50.8
  Bottom 0.254: v51.44,55.88 46.99,55.88 IC5.17 | v53.98,50.8 80.64,50.8 R21.1
N$52  (via drill 0.61)
  Top 0.254: v62.23,47.62 v62.23,38.73 | v53.34,47.62 52.7,48.26 v52.7,53.34
  Bottom 0.254: v62.23,38.73 71.75,38.73 73.03,40.01 80.01,40.01 80.64,40.64 R22.1 | v53.34,47.62 v62.23,47.62 | v52.7,53.34 46.99,53.34 IC5.16
N$53  (via drill 0.61)
  Top 0.254: v78.11,30.48 74.3,34.29 v74.3,45.09 | v66.04,48.26 64.77,49.53 v64.77,55.24
  Bottom 0.254: v78.11,30.48 80.64,27.94 R23.1 | v74.3,45.09 71.12,48.26 v66.04,48.26 | v64.77,55.24 62.87,57.15 59.69,57.15 57.78,55.24 55.24,55.24 53.98,53.98 53.98,52.07 48.9,52.07 47.62,50.8 46.99,50.8 IC5.15
N$54  (via drill 0.61)
  Top 0.254: v79.38,48.26 80.01,47.62 80.01,24.77 81.28,23.5 R24.1
  Bottom 0.254: v79.38,48.26 78.11,48.26 76.83,49.53 66.04,49.53 65.41,48.9 47.62,48.9 46.99,48.26 IC5.14
N$55  (via drill 0.61)
  Top 0.254: v50.8,14.61 50.8,18.41 49.53,19.68 49.53,30.48 48.9,31.11 48.9,35.56 50.16,36.83 v50.16,45.72
  Bottom 0.254: v50.8,14.61 51.44,15.24 78.11,15.24 80.64,12.7 R25.1 | v50.16,45.72 46.99,45.72 IC5.13
N$56  (via drill 0.61)
  Top 0.254: v67.31,6.99 66.04,8.26 66.04,12.06 64.14,13.97 64.14,27.94 v62.87,29.21 | v48.26,25.4 48.26,36.2 48.9,36.83 48.9,40.01 46.35,42.55 IC5.12
  Bottom 0.254: v67.31,6.99 70.48,3.81 71.75,3.81 74.3,6.35 81.92,6.35 84.45,3.81 92.08,3.81 93.34,2.54 R26.1 | v62.87,29.21 55.24,29.21 51.44,25.4 v48.26,25.4
N$57
  Bottom 0.254: LED22.K 97.16,55.88 99.69,58.42 103.5,58.42 R27.2
N$58
  Bottom 0.254: IC6.18 33.02,58.42 35.56,58.42 36.83,59.69 66.67,59.69 68.58,57.78 80.01,57.78 80.64,57.15 92.08,57.15 93.34,58.42 R27.1
N$59
  Top 0.254: R28.2 92.08,48.26 95.89,48.26 LED23.K
N$60
  Bottom 0.254: R29.2 92.08,38.1 94.61,40.64 95.89,40.64 LED24.K
N$61
  Bottom 0.254: R30.2 92.08,30.48 94.61,33.02 95.89,33.02 LED25.K
N$62
  Top 0.254: R31.2 92.08,25.4 95.89,25.4 LED26.K
N$63
  Bottom 0.254: R32.2 92.08,15.24 94.61,17.78 95.89,17.78 LED27.K
N$64
  Top 0.254: LED28.K 97.16,10.16 100.33,10.16 100.33,10.79 100.97,11.43 104.14,11.43 104.14,5.71 R33.2
N$65  (via drill 0.61)
  Top 0.254: v34.29,43.18 34.29,55.24 v34.92,55.88
  Bottom 0.254: v34.29,43.18 35.56,41.91 46.99,41.91 47.62,42.55 64.14,42.55 65.41,43.81 76.2,43.81 80.64,48.26 R28.1 | v34.92,55.88 33.02,55.88 IC6.17
N$66  (via drill 0.61)
  Top 0.254: v83.82,58.42 v83.82,38.1 | v54.61,60.96 50.16,56.52 50.16,46.99 51.44,45.72 v51.44,45.09 | v29.84,44.45 29.84,51.44 31.11,52.7 IC6.16
  Bottom 0.254: v83.82,38.1 81.92,38.1 R29.1 | v83.82,58.42 82.55,59.69 67.94,59.69 66.67,60.96 v54.61,60.96 | v51.44,45.09 50.8,44.45 v29.84,44.45
N$67  (via drill 0.61)
  Top 0.254: v35.56,50.8 36.83,49.53 v40.01,49.53 | v78.11,49.53 v78.11,31.75
  Bottom 0.254: v35.56,50.8 33.02,50.8 IC6.15 | v40.01,49.53 64.77,49.53 65.41,50.16 77.47,50.16 v78.11,49.53 | v78.11,31.75 79.38,30.48 80.64,30.48 R30.1
N$68  (via drill 0.61)
  Top 0.254: v35.56,48.26 36.83,46.99 v40.01,46.99 | v47.62,46.99 48.9,48.26 48.9,57.78 v48.26,58.42 | v53.34,58.42 57.15,62.23 85.09,62.23 v85.09,29.84
  Bottom 0.254: v35.56,48.26 33.02,48.26 IC6.14 | v40.01,46.99 v47.62,46.99 | v48.26,58.42 v53.34,58.42 | v85.09,29.84 81.28,26.04 R31.1
N$69  (via drill 0.61)
  Top 0.254: v35.56,45.72 35.56,43.18 33.66,41.27 v33.66,33.02
  Bottom 0.254: v35.56,45.72 33.02,45.72 IC6.13 | v33.66,33.02 34.29,32.38 52.7,32.38 54.61,30.48 71.75,30.48 80.64,21.59 81.92,21.59 84.45,19.05 84.45,15.88 81.28,15.88 R32.1
N$70  (via drill 0.61)
  Top 0.254: v34.29,59.69 33.66,59.05 33.66,45.09 32.38,43.81 IC6.12 | v41.91,60.96 43.18,59.69 v43.18,58.42 | v86.36,52.07 90.17,48.26 90.17,6.99 90.81,6.35 93.98,6.35 93.98,5.71 R33.1
  Bottom 0.254: v34.29,59.69 35.56,60.96 v41.91,60.96 | v43.18,58.42 44.45,57.15 58.42,57.15 59.05,57.78 63.5,57.78 64.14,57.15 75.56,57.15 80.64,52.07 v86.36,52.07
P1  (via drill 0.61)
  Top 0.254: v40.01,34.92 40.01,27.3 38.73,26.04 IC3.3 | v15.24,40.64 13.97,41.91 U$1.P1
  Bottom 0.254: v40.01,34.92 29.84,34.92 25.4,39.37 16.51,39.37 v15.24,40.64
P2  (via drill 0.61)
  Top 0.254: v20.32,43.18 20.32,58.42 22.86,58.42 IC6.1
  Bottom 0.254: v20.32,43.18 13.97,43.18 U$1.P2
R1  (via drill 0.61)
  Top 0.254: v34.92,22.23 32.38,24.77 32.38,34.92 27.94,39.37 v27.94,41.91 | v15.24,44.45 13.97,45.72 U$1.R1
  Bottom 0.254: v34.92,22.23 36.2,22.23 36.83,22.86 IC3.4 | v27.94,41.91 25.4,44.45 v15.24,44.45
R2  (via drill 0.61)
  Top 0.254: v41.27,15.24 41.27,33.66 41.91,34.29 41.91,53.98 42.55,54.61 v42.55,55.88 | v22.23,57.15 21.59,56.52 v21.59,48.26 | v15.88,48.26 16.51,47.62 16.51,46.99 v15.24,45.72
  Bottom 0.254: v41.27,15.24 39.37,15.24 IC3.7 | v42.55,55.88 41.27,57.15 v22.23,57.15 | v21.59,48.26 v15.88,48.26 | v15.24,45.72 13.97,45.72 U$1.R2
S1  (via drill 0.61)
  Top 0.254: v40.01,11.43 40.01,16.51 36.83,16.51 36.2,17.14 36.2,18.41 37.47,19.68 IC3.5 | v50.8,13.34 52.07,14.61 52.07,18.41 50.16,20.32 v50.16,31.11 | v24.13,35.56 21.59,38.1 v21.59,46.99 | v15.24,46.99 13.97,48.26 U$1.S1
  Bottom 0.254: v40.01,11.43 48.9,11.43 v50.8,13.34 | v50.16,31.11 49.53,31.75 29.21,31.75 25.4,35.56 v24.13,35.56 | v21.59,46.99 v15.24,46.99
S2
  Bottom 0.254: IC5.4 36.83,50.8 35.56,49.53 13.97,49.53 U$1.S2
T2
  Bottom 0.254: IC5.2 36.83,55.88 35.56,54.61 15.88,54.61 13.97,52.7 U$1.T2
U1  (via drill 0.61)
  Top 0.254: v52.07,46.35 51.44,46.99 v51.44,54.61 | v41.27,54.61 40.64,55.24 40.64,62.23 20.32,62.23 20.32,59.69 16.51,55.88 13.97,55.88 U$1.U1
  Bottom 0.254: IC2.12 65.41,45.09 64.14,43.81 57.78,43.81 56.52,45.09 IC2.8 55.24,46.35 v52.07,46.35 | v41.27,54.61 v51.44,54.61
U2
  Bottom 0.254: IC6.2 22.86,55.88 13.97,55.88 U$1.U2
V1  (via drill 0.61)
  Top 0.254: v33.02,60.33 33.02,60.96 34.29,60.96 36.83,58.42 IC5.1 | v15.24,57.78 13.97,57.78 U$1.V1
  Bottom 0.254: v33.02,60.33 32.38,59.69 21.59,59.69 19.68,57.78 v15.24,57.78
V2  (via drill 0.61)
  Top 0.254: v53.98,17.78 51.44,20.32 v51.44,20.95 | v43.81,21.59 43.18,22.23 43.18,31.75 43.81,32.38 43.81,43.81 44.45,44.45 48.9,44.45 48.9,46.99 49.53,47.62 49.53,60.33 47.62,62.23 43.18,62.23 v43.18,60.96
  Bottom 0.254: R1.1 60.96,18.41 60.33,18.41 59.05,19.68 S2.1 57.78,19.68 57.78,17.78 v53.98,17.78 | v51.44,20.95 50.8,21.59 v43.81,21.59 | v43.18,60.96 41.91,62.23 22.86,62.23 19.68,59.05 13.97,59.05 U$1.V2
VCC  (via drill 0.61)
  Top 0.254: R2.2 60.96,5.71 62.87,7.62 v62.87,17.78 v62.87,27.94 | v71.12,29.21 71.12,31.75 IC1.14 71.12,34.29 72.39,35.56 72.39,48.26 | 72.39,48.26 71.12,46.99 IC2.14 | 72.39,48.26 72.39,55.24 71.75,55.88 R3.2 | v68.58,55.88 68.58,56.52 66.67,58.42 R4.2 | v47.62,2.54 48.26,3.17 v48.26,8.89
  Bottom 0.254: v62.87,17.78 70.48,17.78 R1.2 | v71.12,29.21 69.22,29.21 67.94,27.94 v62.87,27.94 60.33,27.94 R5.2 | v68.58,55.88 70.48,55.88 R3.2 | v47.62,2.54 46.99,1.91 20.95,1.91 18.41,4.45 14.61,4.45 U$1.A2 | v48.26,8.89 48.9,8.26 52.07,8.26 55.24,5.08 60.33,5.08 R2.2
